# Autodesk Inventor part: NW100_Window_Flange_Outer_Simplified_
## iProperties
Shininess: 64.0
Length Units: 11269
Angle Units: 11279
Time Units: 11290
Mass Units: 11283
Length Display Precision: 3
Angle Display Precision: 2
Compacted: True
Part Number: NW100_Window_Flange_Outer_Simplified_
Document SubType Name: Modeling
Created: 2004-07
Designer: John Blackburn
Manufacturer: Standard
Standards Organization: Custom
Density: 0.0
Volumn: 0.0
Area: 0.0
PropertySet Name: Model Information
Control State: 0
Master: False
Checked Out: False
Author: John Blackburn
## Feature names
1. Extrusion1
